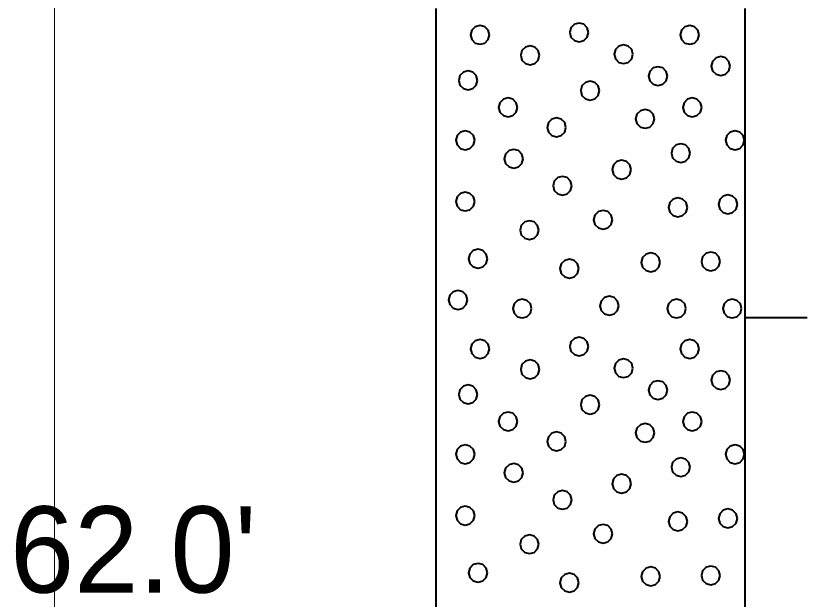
# Model space of a CAD drawing. Extents: x -76 to 974, y -1080 to -735.
# Drawn here: x 133.08 to 139.47, y -991.86 to -987.14 of the extents above; entities that cross this region are included whole.
import ezdxf

# ---------------------------------------------------------------- set-up
doc = ezdxf.new("R2010")
doc.units = 0
doc.header["$LTSCALE"] = 0.36
doc.layers.add('27', color=7, linetype='Continuous', lineweight=40)
doc.layers.add('7', color=7, linetype='Continuous', lineweight=13)

msp = doc.modelspace()

# ---------------------------------------------------------------- linework, layer by layer
at = {"layer": '27'}
for p, q in [((136.4742, -987.0789), (136.4742, -992.0789)), ((138.9742, -992.0789), (138.9742, -987.0789)), ((139.4742, -989.5789), (138.9742, -989.5789))]:
    msp.add_line(p, q, dxfattribs=at)
for points in [[(136.9061, -987.2916), (136.8959, -987.2535), (136.868, -987.2256), (136.8299, -987.2154), (136.7918, -987.2256), (136.7639, -987.2535), (136.7537, -987.2916), (136.7639, -987.3297), (136.7918, -987.3575), (136.8299, -987.3678), (136.868, -987.3575), (136.8959, -987.3297)], [(137.7071, -987.272), (137.6969, -987.2339), (137.669, -987.206), (137.6309, -987.1958), (137.5928, -987.206), (137.5649, -987.2339), (137.5547, -987.272), (137.5649, -987.3101), (137.5928, -987.338), (137.6309, -987.3482), (137.669, -987.338), (137.6969, -987.3101)], [(138.6007, -987.2916), (138.5905, -987.2535), (138.5626, -987.2256), (138.5245, -987.2154), (138.4864, -987.2256), (138.4585, -987.2535), (138.4483, -987.2916), (138.4585, -987.3297), (138.4864, -987.3576), (138.5245, -987.3678), (138.5626, -987.3576), (138.5905, -987.3297)], [(137.3111, -987.4568), (137.3009, -987.4187), (137.273, -987.3908), (137.2349, -987.3806), (137.1968, -987.3908), (137.1689, -987.4187), (137.1587, -987.4568), (137.1689, -987.4949), (137.1968, -987.5228), (137.2349, -987.533), (137.273, -987.5228), (137.3009, -987.4949)], [(138.0662, -987.4478), (138.0559, -987.4097), (138.0281, -987.3818), (137.99, -987.3716), (137.9519, -987.3818), (137.924, -987.4097), (137.9138, -987.4478), (137.924, -987.4859), (137.9519, -987.5138), (137.99, -987.524), (138.0281, -987.5138), (138.0559, -987.4859)], [(138.8516, -987.5437), (138.8414, -987.5056), (138.8135, -987.4777), (138.7754, -987.4675), (138.7373, -987.4777), (138.7094, -987.5056), (138.6992, -987.5437), (138.7094, -987.5818), (138.7373, -987.6097), (138.7754, -987.6199), (138.8135, -987.6097), (138.8414, -987.5818)], [(136.8099, -987.6594), (136.7997, -987.6213), (136.7718, -987.5934), (136.7337, -987.5832), (136.6956, -987.5934), (136.6678, -987.6213), (136.6575, -987.6594), (136.6678, -987.6975), (136.6956, -987.7254), (136.7337, -987.7356), (136.7718, -987.7254), (136.7997, -987.6975)], [(138.3444, -987.6251), (138.3342, -987.587), (138.3063, -987.5591), (138.2682, -987.5489), (138.2301, -987.5591), (138.2022, -987.587), (138.192, -987.6251), (138.2022, -987.6632), (138.2301, -987.6911), (138.2682, -987.7013), (138.3063, -987.6911), (138.3342, -987.6632)], [(137.796, -987.7426), (137.7858, -987.7045), (137.7579, -987.6766), (137.7198, -987.6664), (137.6817, -987.6766), (137.6538, -987.7045), (137.6436, -987.7426), (137.6538, -987.7807), (137.6817, -987.8086), (137.7198, -987.8188), (137.7579, -987.8086), (137.7858, -987.7807)], [(137.1328, -987.8781), (137.1226, -987.84), (137.0947, -987.8121), (137.0566, -987.8019), (137.0185, -987.8121), (136.9907, -987.84), (136.9804, -987.8781), (136.9907, -987.9162), (137.0185, -987.9441), (137.0566, -987.9543), (137.0947, -987.9441), (137.1226, -987.9162)], [(138.6215, -987.8781), (138.6113, -987.84), (138.5834, -987.8121), (138.5453, -987.8019), (138.5072, -987.8121), (138.4793, -987.84), (138.4691, -987.8781), (138.4793, -987.9162), (138.5072, -987.9441), (138.5453, -987.9543), (138.5834, -987.9441), (138.6113, -987.9162)], [(138.2401, -987.9709), (138.2299, -987.9328), (138.202, -987.9049), (138.1639, -987.8947), (138.1258, -987.9049), (138.0979, -987.9328), (138.0877, -987.9709), (138.0979, -988.009), (138.1258, -988.0369), (138.1639, -988.0471), (138.202, -988.0369), (138.2299, -988.009)], [(137.5244, -988.0395), (137.5142, -988.0014), (137.4863, -987.9735), (137.4482, -987.9633), (137.4101, -987.9735), (137.3822, -988.0014), (137.372, -988.0395), (137.3822, -988.0776), (137.4101, -988.1055), (137.4482, -988.1157), (137.4863, -988.1055), (137.5142, -988.0776)], [(136.7871, -988.1438), (136.7769, -988.1057), (136.749, -988.0778), (136.7109, -988.0676), (136.6728, -988.0778), (136.6449, -988.1057), (136.6347, -988.1438), (136.6449, -988.1819), (136.6728, -988.2097), (136.7109, -988.22), (136.749, -988.2097), (136.7769, -988.1819)], [(138.9673, -988.1438), (138.9571, -988.1057), (138.9292, -988.0778), (138.8911, -988.0676), (138.853, -988.0778), (138.8251, -988.1057), (138.8149, -988.1438), (138.8251, -988.1819), (138.853, -988.2097), (138.8911, -988.22), (138.9292, -988.2097), (138.9571, -988.1819)], [(138.5287, -988.248), (138.5185, -988.2099), (138.4906, -988.182), (138.4525, -988.1718), (138.4144, -988.182), (138.3865, -988.2099), (138.3763, -988.248), (138.3865, -988.2861), (138.4144, -988.314), (138.4525, -988.3242), (138.4906, -988.314), (138.5185, -988.2861)], [(137.1786, -988.2938), (137.1684, -988.2557), (137.1405, -988.2278), (137.1024, -988.2176), (137.0643, -988.2278), (137.0364, -988.2557), (137.0262, -988.2938), (137.0364, -988.3319), (137.0643, -988.3598), (137.1024, -988.37), (137.1405, -988.3598), (137.1684, -988.3319)], [(138.0507, -988.3815), (138.0405, -988.3434), (138.0126, -988.3155), (137.9745, -988.3053), (137.9364, -988.3155), (137.9085, -988.3434), (137.8983, -988.3815), (137.9085, -988.4196), (137.9364, -988.4475), (137.9745, -988.4577), (138.0126, -988.4475), (138.0405, -988.4196)], [(137.5727, -988.5124), (137.5625, -988.4743), (137.5346, -988.4464), (137.4965, -988.4362), (137.4584, -988.4464), (137.4305, -988.4743), (137.4203, -988.5124), (137.4305, -988.5505), (137.4584, -988.5784), (137.4965, -988.5886), (137.5346, -988.5784), (137.5625, -988.5505)], [(136.7871, -988.6396), (136.7769, -988.6015), (136.749, -988.5736), (136.7109, -988.5634), (136.6728, -988.5736), (136.6449, -988.6015), (136.6347, -988.6396), (136.6449, -988.6777), (136.6728, -988.7055), (136.7109, -988.7158), (136.749, -988.7055), (136.7769, -988.6777)], [(138.5058, -988.6866), (138.4956, -988.6485), (138.4677, -988.6206), (138.4296, -988.6104), (138.3915, -988.6206), (138.3636, -988.6485), (138.3534, -988.6866), (138.3636, -988.7247), (138.3915, -988.7526), (138.4296, -988.7628), (138.4677, -988.7526), (138.4956, -988.7247)], [(138.9101, -988.6624), (138.8999, -988.6243), (138.872, -988.5964), (138.8339, -988.5862), (138.7958, -988.5964), (138.7679, -988.6243), (138.7577, -988.6624), (138.7679, -988.7005), (138.7958, -988.7284), (138.8339, -988.7386), (138.872, -988.7284), (138.8999, -988.7005)], [(137.9007, -988.787), (137.8905, -988.7489), (137.8626, -988.721), (137.8245, -988.7108), (137.7864, -988.721), (137.7585, -988.7489), (137.7483, -988.787), (137.7585, -988.8251), (137.7864, -988.853), (137.8245, -988.8632), (137.8626, -988.853), (137.8905, -988.8251)], [(137.3057, -988.8709), (137.2955, -988.8328), (137.2676, -988.8049), (137.2295, -988.7947), (137.1914, -988.8049), (137.1636, -988.8328), (137.1533, -988.8709), (137.1636, -988.909), (137.1914, -988.9369), (137.2295, -988.9471), (137.2676, -988.9369), (137.2955, -988.909)], [(136.89, -989.1023), (136.8798, -989.0642), (136.8519, -989.0363), (136.8138, -989.0261), (136.7757, -989.0363), (136.7478, -989.0642), (136.7376, -989.1023), (136.7478, -989.1404), (136.7757, -989.1683), (136.8138, -989.1785), (136.8519, -989.1683), (136.8798, -989.1404)], [(138.2859, -989.1315), (138.2757, -989.0934), (138.2478, -989.0655), (138.2097, -989.0553), (138.1716, -989.0655), (138.1437, -989.0934), (138.1335, -989.1315), (138.1437, -989.1696), (138.1716, -989.1975), (138.2097, -989.2077), (138.2478, -989.1975), (138.2757, -989.1696)], [(138.7715, -989.1239), (138.7613, -989.0858), (138.7334, -989.0579), (138.6953, -989.0477), (138.6572, -989.0579), (138.6293, -989.0858), (138.6191, -989.1239), (138.6293, -989.162), (138.6572, -989.1899), (138.6953, -989.2001), (138.7334, -989.1899), (138.7613, -989.162)], [(137.6286, -989.1824), (137.6184, -989.1443), (137.5905, -989.1164), (137.5524, -989.1062), (137.5143, -989.1164), (137.4865, -989.1443), (137.4762, -989.1824), (137.4865, -989.2205), (137.5143, -989.2484), (137.5524, -989.2586), (137.5905, -989.2484), (137.6184, -989.2205)], [(136.7286, -989.4354), (136.7184, -989.3973), (136.6905, -989.3694), (136.6524, -989.3592), (136.6143, -989.3694), (136.5864, -989.3973), (136.5762, -989.4354), (136.5864, -989.4735), (136.6143, -989.5014), (136.6524, -989.5116), (136.6905, -989.5014), (136.7184, -989.4735)], [(137.2473, -989.5053), (137.2371, -989.4672), (137.2092, -989.4393), (137.1711, -989.4291), (137.133, -989.4393), (137.1051, -989.4672), (137.0949, -989.5053), (137.1051, -989.5434), (137.133, -989.5713), (137.1711, -989.5815), (137.2092, -989.5713), (137.2371, -989.5434)], [(137.9515, -989.4824), (137.9413, -989.4443), (137.9134, -989.4164), (137.8753, -989.4062), (137.8372, -989.4164), (137.8094, -989.4443), (137.7991, -989.4824), (137.8094, -989.5205), (137.8372, -989.5484), (137.8753, -989.5586), (137.9134, -989.5484), (137.9413, -989.5205)], [(138.4944, -989.5053), (138.4842, -989.4672), (138.4563, -989.4393), (138.4182, -989.4291), (138.3801, -989.4393), (138.3522, -989.4672), (138.342, -989.5053), (138.3522, -989.5434), (138.3801, -989.5713), (138.4182, -989.5815), (138.4563, -989.5713), (138.4842, -989.5434)], [(138.9444, -989.5053), (138.9342, -989.4672), (138.9063, -989.4393), (138.8682, -989.4291), (138.8301, -989.4393), (138.8022, -989.4672), (138.792, -989.5053), (138.8022, -989.5434), (138.8301, -989.5713), (138.8682, -989.5815), (138.9063, -989.5713), (138.9342, -989.5434)], [(136.9061, -989.8316), (136.8959, -989.7935), (136.868, -989.7656), (136.8299, -989.7554), (136.7918, -989.7656), (136.7639, -989.7935), (136.7537, -989.8316), (136.7639, -989.8697), (136.7918, -989.8975), (136.8299, -989.9078), (136.868, -989.8975), (136.8959, -989.8697)], [(137.7071, -989.812), (137.6969, -989.7739), (137.669, -989.746), (137.6309, -989.7358), (137.5928, -989.746), (137.5649, -989.7739), (137.5547, -989.812), (137.5649, -989.8501), (137.5928, -989.878), (137.6309, -989.8882), (137.669, -989.878), (137.6969, -989.8501)], [(138.6007, -989.8316), (138.5905, -989.7935), (138.5626, -989.7656), (138.5245, -989.7554), (138.4864, -989.7656), (138.4585, -989.7935), (138.4483, -989.8316), (138.4585, -989.8697), (138.4864, -989.8976), (138.5245, -989.9078), (138.5626, -989.8976), (138.5905, -989.8697)], [(138.0662, -989.9878), (138.0559, -989.9497), (138.0281, -989.9218), (137.99, -989.9116), (137.9519, -989.9218), (137.924, -989.9497), (137.9138, -989.9878), (137.924, -990.0259), (137.9519, -990.0538), (137.99, -990.064), (138.0281, -990.0538), (138.0559, -990.0259)], [(137.3111, -989.9968), (137.3009, -989.9587), (137.273, -989.9308), (137.2349, -989.9206), (137.1968, -989.9308), (137.1689, -989.9587), (137.1587, -989.9968), (137.1689, -990.0349), (137.1968, -990.0628), (137.2349, -990.073), (137.273, -990.0628), (137.3009, -990.0349)], [(138.8516, -990.0837), (138.8414, -990.0456), (138.8135, -990.0177), (138.7754, -990.0075), (138.7373, -990.0177), (138.7094, -990.0456), (138.6992, -990.0837), (138.7094, -990.1218), (138.7373, -990.1497), (138.7754, -990.1599), (138.8135, -990.1497), (138.8414, -990.1218)], [(138.3444, -990.1651), (138.3342, -990.127), (138.3063, -990.0991), (138.2682, -990.0889), (138.2301, -990.0991), (138.2022, -990.127), (138.192, -990.1651), (138.2022, -990.2032), (138.2301, -990.2311), (138.2682, -990.2413), (138.3063, -990.2311), (138.3342, -990.2032)], [(136.8099, -990.1994), (136.7997, -990.1613), (136.7718, -990.1334), (136.7337, -990.1232), (136.6956, -990.1334), (136.6678, -990.1613), (136.6575, -990.1994), (136.6678, -990.2375), (136.6956, -990.2654), (136.7337, -990.2756), (136.7718, -990.2654), (136.7997, -990.2375)], [(137.796, -990.2826), (137.7858, -990.2445), (137.7579, -990.2166), (137.7198, -990.2064), (137.6817, -990.2166), (137.6538, -990.2445), (137.6436, -990.2826), (137.6538, -990.3207), (137.6817, -990.3486), (137.7198, -990.3588), (137.7579, -990.3486), (137.7858, -990.3207)], [(137.1328, -990.4181), (137.1226, -990.38), (137.0947, -990.3521), (137.0566, -990.3419), (137.0185, -990.3521), (136.9907, -990.38), (136.9804, -990.4181), (136.9907, -990.4562), (137.0185, -990.4841), (137.0566, -990.4943), (137.0947, -990.4841), (137.1226, -990.4562)], [(138.6215, -990.4181), (138.6113, -990.38), (138.5834, -990.3521), (138.5453, -990.3419), (138.5072, -990.3521), (138.4793, -990.38), (138.4691, -990.4181), (138.4793, -990.4562), (138.5072, -990.4841), (138.5453, -990.4943), (138.5834, -990.4841), (138.6113, -990.4562)], [(138.2401, -990.5109), (138.2299, -990.4728), (138.202, -990.4449), (138.1639, -990.4347), (138.1258, -990.4449), (138.0979, -990.4728), (138.0877, -990.5109), (138.0979, -990.549), (138.1258, -990.5769), (138.1639, -990.5871), (138.202, -990.5769), (138.2299, -990.549)], [(137.5244, -990.5795), (137.5142, -990.5414), (137.4863, -990.5135), (137.4482, -990.5033), (137.4101, -990.5135), (137.3822, -990.5414), (137.372, -990.5795), (137.3822, -990.6176), (137.4101, -990.6455), (137.4482, -990.6557), (137.4863, -990.6455), (137.5142, -990.6176)], [(136.7871, -990.6838), (136.7769, -990.6457), (136.749, -990.6178), (136.7109, -990.6076), (136.6728, -990.6178), (136.6449, -990.6457), (136.6347, -990.6838), (136.6449, -990.7219), (136.6728, -990.7497), (136.7109, -990.76), (136.749, -990.7497), (136.7769, -990.7219)], [(138.9673, -990.6838), (138.9571, -990.6457), (138.9292, -990.6178), (138.8911, -990.6076), (138.853, -990.6178), (138.8251, -990.6457), (138.8149, -990.6838), (138.8251, -990.7219), (138.853, -990.7497), (138.8911, -990.76), (138.9292, -990.7497), (138.9571, -990.7219)], [(138.5287, -990.788), (138.5185, -990.7499), (138.4906, -990.722), (138.4525, -990.7118), (138.4144, -990.722), (138.3865, -990.7499), (138.3763, -990.788), (138.3865, -990.8261), (138.4144, -990.854), (138.4525, -990.8642), (138.4906, -990.854), (138.5185, -990.8261)], [(137.1786, -990.8338), (137.1684, -990.7957), (137.1405, -990.7678), (137.1024, -990.7576), (137.0643, -990.7678), (137.0364, -990.7957), (137.0262, -990.8338), (137.0364, -990.8719), (137.0643, -990.8998), (137.1024, -990.91), (137.1405, -990.8998), (137.1684, -990.8719)], [(138.0507, -990.9215), (138.0405, -990.8834), (138.0126, -990.8555), (137.9745, -990.8453), (137.9364, -990.8555), (137.9085, -990.8834), (137.8983, -990.9215), (137.9085, -990.9596), (137.9364, -990.9875), (137.9745, -990.9977), (138.0126, -990.9875), (138.0405, -990.9596)], [(137.5727, -991.0524), (137.5625, -991.0143), (137.5346, -990.9864), (137.4965, -990.9762), (137.4584, -990.9864), (137.4305, -991.0143), (137.4203, -991.0524), (137.4305, -991.0905), (137.4584, -991.1184), (137.4965, -991.1286), (137.5346, -991.1184), (137.5625, -991.0905)], [(136.7871, -991.1796), (136.7769, -991.1415), (136.749, -991.1136), (136.7109, -991.1034), (136.6728, -991.1136), (136.6449, -991.1415), (136.6347, -991.1796), (136.6449, -991.2177), (136.6728, -991.2455), (136.7109, -991.2558), (136.749, -991.2455), (136.7769, -991.2177)], [(138.9101, -991.2024), (138.8999, -991.1643), (138.872, -991.1364), (138.8339, -991.1262), (138.7958, -991.1364), (138.7679, -991.1643), (138.7577, -991.2024), (138.7679, -991.2405), (138.7958, -991.2684), (138.8339, -991.2786), (138.872, -991.2684), (138.8999, -991.2405)], [(138.5058, -991.2266), (138.4956, -991.1885), (138.4677, -991.1606), (138.4296, -991.1504), (138.3915, -991.1606), (138.3636, -991.1885), (138.3534, -991.2266), (138.3636, -991.2647), (138.3915, -991.2926), (138.4296, -991.3028), (138.4677, -991.2926), (138.4956, -991.2647)], [(137.9007, -991.327), (137.8905, -991.2889), (137.8626, -991.261), (137.8245, -991.2508), (137.7864, -991.261), (137.7585, -991.2889), (137.7483, -991.327), (137.7585, -991.3651), (137.7864, -991.393), (137.8245, -991.4032), (137.8626, -991.393), (137.8905, -991.3651)], [(137.3057, -991.4109), (137.2955, -991.3728), (137.2676, -991.3449), (137.2295, -991.3347), (137.1914, -991.3449), (137.1636, -991.3728), (137.1533, -991.4109), (137.1636, -991.449), (137.1914, -991.4769), (137.2295, -991.4871), (137.2676, -991.4769), (137.2955, -991.449)], [(136.89, -991.6423), (136.8798, -991.6042), (136.8519, -991.5763), (136.8138, -991.5661), (136.7757, -991.5763), (136.7478, -991.6042), (136.7376, -991.6423), (136.7478, -991.6804), (136.7757, -991.7083), (136.8138, -991.7185), (136.8519, -991.7083), (136.8798, -991.6804)], [(138.2859, -991.6715), (138.2757, -991.6334), (138.2478, -991.6055), (138.2097, -991.5953), (138.1716, -991.6055), (138.1437, -991.6334), (138.1335, -991.6715), (138.1437, -991.7096), (138.1716, -991.7375), (138.2097, -991.7477), (138.2478, -991.7375), (138.2757, -991.7096)], [(138.7715, -991.6639), (138.7613, -991.6258), (138.7334, -991.5979), (138.6953, -991.5877), (138.6572, -991.5979), (138.6293, -991.6258), (138.6191, -991.6639), (138.6293, -991.702), (138.6572, -991.7299), (138.6953, -991.7401), (138.7334, -991.7299), (138.7613, -991.702)], [(137.6286, -991.7224), (137.6184, -991.6843), (137.5905, -991.6564), (137.5524, -991.6462), (137.5143, -991.6564), (137.4865, -991.6843), (137.4762, -991.7224), (137.4865, -991.7605), (137.5143, -991.7884), (137.5524, -991.7986), (137.5905, -991.7884), (137.6184, -991.7605)]]:
    msp.add_lwpolyline(points, close=True, dxfattribs=at)
at = {"layer": '7'}
msp.add_line((133.3912, -1033.3123), (133.3912, -895.7205), dxfattribs=at)

# ---------------------------------------------------------------- texts
at = {"layer": '27'}
msp.add_text("62.0'", height=0.6976, dxfattribs=at).set_placement((133.0308, -991.8025))

doc.saveas('drawing.dxf')
